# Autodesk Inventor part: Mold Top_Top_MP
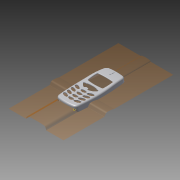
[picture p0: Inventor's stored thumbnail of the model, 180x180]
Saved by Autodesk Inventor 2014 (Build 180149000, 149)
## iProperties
Created: 2009-12
Part Number: Mold Top_Top_MP
Document SubType Name: Modeling
Designer: gaom
Density: 1 g/cm^3
Material: Generic
Appearance: Default
Author: gaom
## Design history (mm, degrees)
derived "Top.ipt"
node "Mold Top_Top_WP"
patch "Boundary Patch1" dims "d8" = 10, "d9" = 10, "d10" = 10, "d11" = 10, "d12" = 0
patch "Boundary Patch2" dims "d13" = 10, "d14" = 10, "d15" = 10, "d16" = 10, "d17" = 0
patch "Boundary Patch3" dims "d18" = 10, "d19" = 10, "d20" = 10, "d21" = 10, "d22" = 10, "d23" = 10, "d24" = 10, "d25" = 10, "d26" = 10, "d27" = 10, "d28" = 10, "d29" = 10, "d30" = 10, "d31" = 10, "d32" = 10, "d33" = 10, "d34" = 10, "d35" = 10, "d36" = 0
patch "Boundary Patch4" dims "d37" = 10, "d38" = 10, "d39" = 10, "d40" = 10, "d41" = 0
patch "Boundary Patch5" dims "d42" = 10, "d43" = 10, "d44" = 10, "d45" = 10, "d46" = 0
patch "Boundary Patch6" dims "d47" = 10, "d48" = 10, "d49" = 10, "d50" = 10, "d51" = 10, "d52" = 10, "d53" = 10, "d54" = 10, "d55" = 0
patch "Boundary Patch7" dims "d56" = 10, "d57" = 10, "d58" = 10, "d59" = 10, "d60" = 0
patch "Boundary Patch8" dims "d61" = 10, "d62" = 10, "d63" = 10, "d64" = 10, "d65" = 0
patch "Boundary Patch9" dims "d66" = 10, "d67" = 10, "d68" = 10, "d69" = 10, "d70" = 0
patch "Boundary Patch10" dims "d71" = 10, "d72" = 10, "d73" = 10, "d74" = 10, "d75" = 0
patch "Boundary Patch11" dims "d76" = 10, "d77" = 0
patch "Boundary Patch12" dims "d78" = 10, "d79" = 0
patch "Boundary Patch13" dims "d80" = 10, "d81" = 0
patch "Boundary Patch14" dims "d82" = 10, "d83" = 0
patch "Boundary Patch15" dims "d84" = 10, "d85" = 0
patch "Boundary Patch16" dims "d86" = 10, "d87" = 10, "d88" = 10, "d89" = 10, "d90" = 0
patch "Boundary Patch17" dims "d91" = 10, "d92" = 10, "d93" = 10, "d94" = 10, "d95" = 0
patch "Boundary Patch18" dims "d96" = 10, "d97" = 10, "d98" = 10, "d99" = 10, "d100" = 0
patch "Boundary Patch19" dims "d101" = 10, "d102" = 10, "d103" = 10, "d104" = 10, "d105" = 0
node "Runoff1" dims "Xmax" = 40, "Xmin" = -40, "Ymax" = 80, "Ymin" = -80, "Zmax" = 25, "Zmin" = -25
node "Runoff2" dims "Xmax" = 40, "Xmin" = -40, "Ymax" = 80, "Ymin" = -80, "Zmax" = 25, "Zmin" = -25
node "Runoff3" dims "Xmax" = 40, "Xmin" = -40, "Ymax" = 80, "Ymin" = -80, "Zmax" = 25, "Zmin" = -25
node "Runoff4" dims "Xmax" = 40, "Xmin" = -40, "Ymax" = 80, "Ymin" = -80, "Zmax" = 25, "Zmin" = -25
node "Runoff5" dims "Xmax" = 40, "Xmin" = -40, "Ymax" = 80, "Ymin" = -80, "Zmax" = 25, "Zmin" = -25
node "Runoff6" dims "Xmax" = 40, "Xmin" = -40, "Ymax" = 80, "Ymin" = -80, "Zmax" = 25, "Zmin" = -25
node "Runoff7" dims "Xmax" = 40, "Xmin" = -40, "Ymax" = 80, "Ymin" = -80, "Zmax" = 25, "Zmin" = -25
node "Runoff8" dims "Xmax" = 40, "Xmin" = -40, "Ymax" = 80, "Ymin" = -80, "Zmax" = 25, "Zmin" = -25
node "Runoff9" dims "Xmax" = 40, "Xmin" = -40, "Ymax" = 80, "Ymin" = -80, "Zmax" = 25, "Zmin" = -25
node "Runoff10" dims "Xmax" = 40, "Xmin" = -40, "Ymax" = 80, "Ymin" = -80, "Zmax" = 25, "Zmin" = -25
node "Runoff11" dims "Xmax" = 40, "Xmin" = -40, "Ymax" = 80, "Ymin" = -80, "Zmax" = 25, "Zmin" = -25
node "Runoff12" dims "Xmax" = 40, "Xmin" = -40, "Ymax" = 80, "Ymin" = -80, "Zmax" = 25, "Zmin" = -25
node "Runoff13" dims "Xmax" = 40, "Xmin" = -40, "Ymax" = 80, "Ymin" = -80, "Zmax" = 25, "Zmin" = -25
node "Runoff14" dims "Xmax" = 40, "Xmin" = -40, "Ymax" = 80, "Ymin" = -80, "Zmax" = 25, "Zmin" = -25
node "Runoff15" dims "Xmax" = 40, "Xmin" = -40, "Ymax" = 80, "Ymin" = -80, "Zmax" = 25, "Zmin" = -25
node "Runoff16" dims "Xmax" = 40, "Xmin" = -40, "Ymax" = 80, "Ymin" = -80, "Zmax" = 25, "Zmin" = -25
node "Runoff17" dims "Xmax" = 40, "Xmin" = -40, "Ymax" = 80, "Ymin" = -80, "Zmax" = 25, "Zmin" = -25
node "Runoff18" dims "Xmax" = 40, "Xmin" = -40, "Ymax" = 80, "Ymin" = -80, "Zmax" = 25, "Zmin" = -25
node "Runoff19" dims "Xmax" = 40, "Xmin" = -40, "Ymax" = 80, "Ymin" = -80, "Zmax" = 25, "Zmin" = -25
node "Runoff20" dims "Xmax" = 40, "Xmin" = -40, "Ymax" = 80, "Ymin" = -80, "Zmax" = 25, "Zmin" = -25
node "Runoff21" dims "Xmax" = 40, "Xmin" = -40, "Ymax" = 80, "Ymin" = -80, "Zmax" = 25, "Zmin" = -25
node "Runoff22" dims "Xmax" = 40, "Xmin" = -40, "Ymax" = 80, "Ymin" = -80, "Zmax" = 25, "Zmin" = -25
node "Runoff23" dims "Xmax" = 40, "Xmin" = -40, "Ymax" = 80, "Ymin" = -80, "Zmax" = 25, "Zmin" = -25
node "Runoff24" dims "Xmax" = 40, "Xmin" = -40, "Ymax" = 80, "Ymin" = -80, "Zmax" = 25, "Zmin" = -25
node "Runoff25" dims "Xmax" = 40, "Xmin" = -40, "Ymax" = 80, "Ymin" = -80, "Zmax" = 25, "Zmin" = -25
node "Runoff26" dims "Xmax" = 40, "Xmin" = -40, "Ymax" = 80, "Ymin" = -80, "Zmax" = 25, "Zmin" = -25
node "Runoff27" dims "Xmax" = 40, "Xmin" = -40, "Ymax" = 80, "Ymin" = -80, "Zmax" = 25, "Zmin" = -25
node "Runoff28" dims "Xmax" = 40, "Xmin" = -40, "Ymax" = 80, "Ymin" = -80, "Zmax" = 25, "Zmin" = -25
node "Runoff29" dims "Xmax" = 40, "Xmin" = -40, "Ymax" = 80, "Ymin" = -80, "Zmax" = 25, "Zmin" = -25
node "Runoff30" dims "Xmax" = 40, "Xmin" = -40, "Ymax" = 80, "Ymin" = -80, "Zmax" = 25, "Zmin" = -25
node "Runoff31" dims "Xmax" = 40, "Xmin" = -40, "Ymax" = 80, "Ymin" = -80, "Zmax" = 25, "Zmin" = -25
node "Runoff32" dims "Xmax" = 40, "Xmin" = -40, "Ymax" = 80, "Ymin" = -80, "Zmax" = 25, "Zmin" = -25
node "Runoff33" dims "Xmax" = 40, "Xmin" = -40, "Ymax" = 80, "Ymin" = -80, "Zmax" = 25, "Zmin" = -25
node "Runoff34" dims "Xmax" = 40, "Xmin" = -40, "Ymax" = 80, "Ymin" = -80, "Zmax" = 25, "Zmin" = -25
node "Runoff35" dims "Xmax" = 40, "Xmin" = -40, "Ymax" = 80, "Ymin" = -80, "Zmax" = 25, "Zmin" = -25
node "Runoff36" dims "Xmax" = 40, "Xmin" = -40, "Ymax" = 80, "Ymin" = -80, "Zmax" = 25, "Zmin" = -25
node "Runoff37" dims "Xmax" = 40, "Xmin" = -40, "Ymax" = 80, "Ymin" = -80, "Zmax" = 25, "Zmin" = -25
node "Runoff38" dims "Xmax" = 40, "Xmin" = -40, "Ymax" = 80, "Ymin" = -80, "Zmax" = 25, "Zmin" = -25
node "Runoff39" dims "Xmax" = 40, "Xmin" = -40, "Ymax" = 80, "Ymin" = -80, "Zmax" = 25, "Zmin" = -25
node "Runoff40" dims "Xmax" = 40, "Xmin" = -40, "Ymax" = 80, "Ymin" = -80, "Zmax" = 25, "Zmin" = -25
node "Runoff41" dims "Xmax" = 40, "Xmin" = -40, "Ymax" = 80, "Ymin" = -80, "Zmax" = 25, "Zmin" = -25
feature "Cavity Separation1"
workplane "Work Plane1"
node "Mold Top_Top_IN3_Base"
feature "Solid1::Top.ipt"
tag "TaggingFeature1"
feature "Solid1::Mold Top_Top_WP"
tag "TaggingFeature2"
body "Srf1"
body "Srf2"
body "Srf3"
body "Srf4"
body "Srf5"
body "Srf6"
body "Srf7"
body "Srf8"
body "Srf9"
body "Srf10"
body "Srf11"
body "Srf12"
body "Srf13"
body "Srf14"
body "Srf15"
body "Srf16"
body "Srf17"
body "Srf18"
body "Srf19"
body "Solid3"
body "Solid4"
feature "Solid2::Mold Top_Top_IN3_Base"
tag "TaggingFeature4"
body "Solid1"
body "Solid2"
feature "Surface1"
body "Srf20"
feature "Surface2"
body "Srf21"
feature "Surface3"
body "Srf22"
feature "Surface4"
body "Srf23"
feature "Surface5"
body "Srf24"
feature "Surface6"
body "Srf25"
feature "Surface7"
body "Srf26"
feature "Surface8"
body "Srf27"
feature "Surface9"
body "Srf28"
feature "Surface10"
body "Srf29"
feature "Surface11"
body "Srf30"
feature "Surface12"
body "Srf31"
feature "Surface13"
body "Srf32"
feature "Surface14"
body "Srf33"
feature "Surface15"
body "Srf34"
feature "Surface16"
body "Srf35"
feature "Surface17"
body "Srf36"
feature "Surface18"
body "Srf37"
feature "Surface19"
body "Srf38"
feature "Surface20"
body "Srf39"
feature "Surface21"
body "Srf40"
feature "Surface22"
body "Srf41"
feature "Surface23"
body "Srf42"
feature "Surface24"
body "Srf43"
feature "Surface25"
body "Srf44"
feature "Surface26"
body "Srf45"
feature "Surface27"
body "Srf46"
feature "Surface28"
body "Srf47"
feature "Surface29"
body "Srf48"
feature "Surface30"
body "Srf49"
feature "Surface31"
body "Srf50"
feature "Surface32"
body "Srf51"
feature "Surface33"
body "Srf52"
feature "Surface34"
body "Srf53"
feature "Surface35"
body "Srf54"
feature "Surface36"
body "Srf55"
feature "Surface37"
body "Srf56"
feature "Surface38"
body "Srf57"
feature "Surface39"
body "Srf58"
feature "Surface40"
body "Srf59"
feature "Surface41"
body "Srf60"
body "Solid6"
other parameters: "d0" = -25, "d6" = 0, "d7" = 5, "d106" = 5
